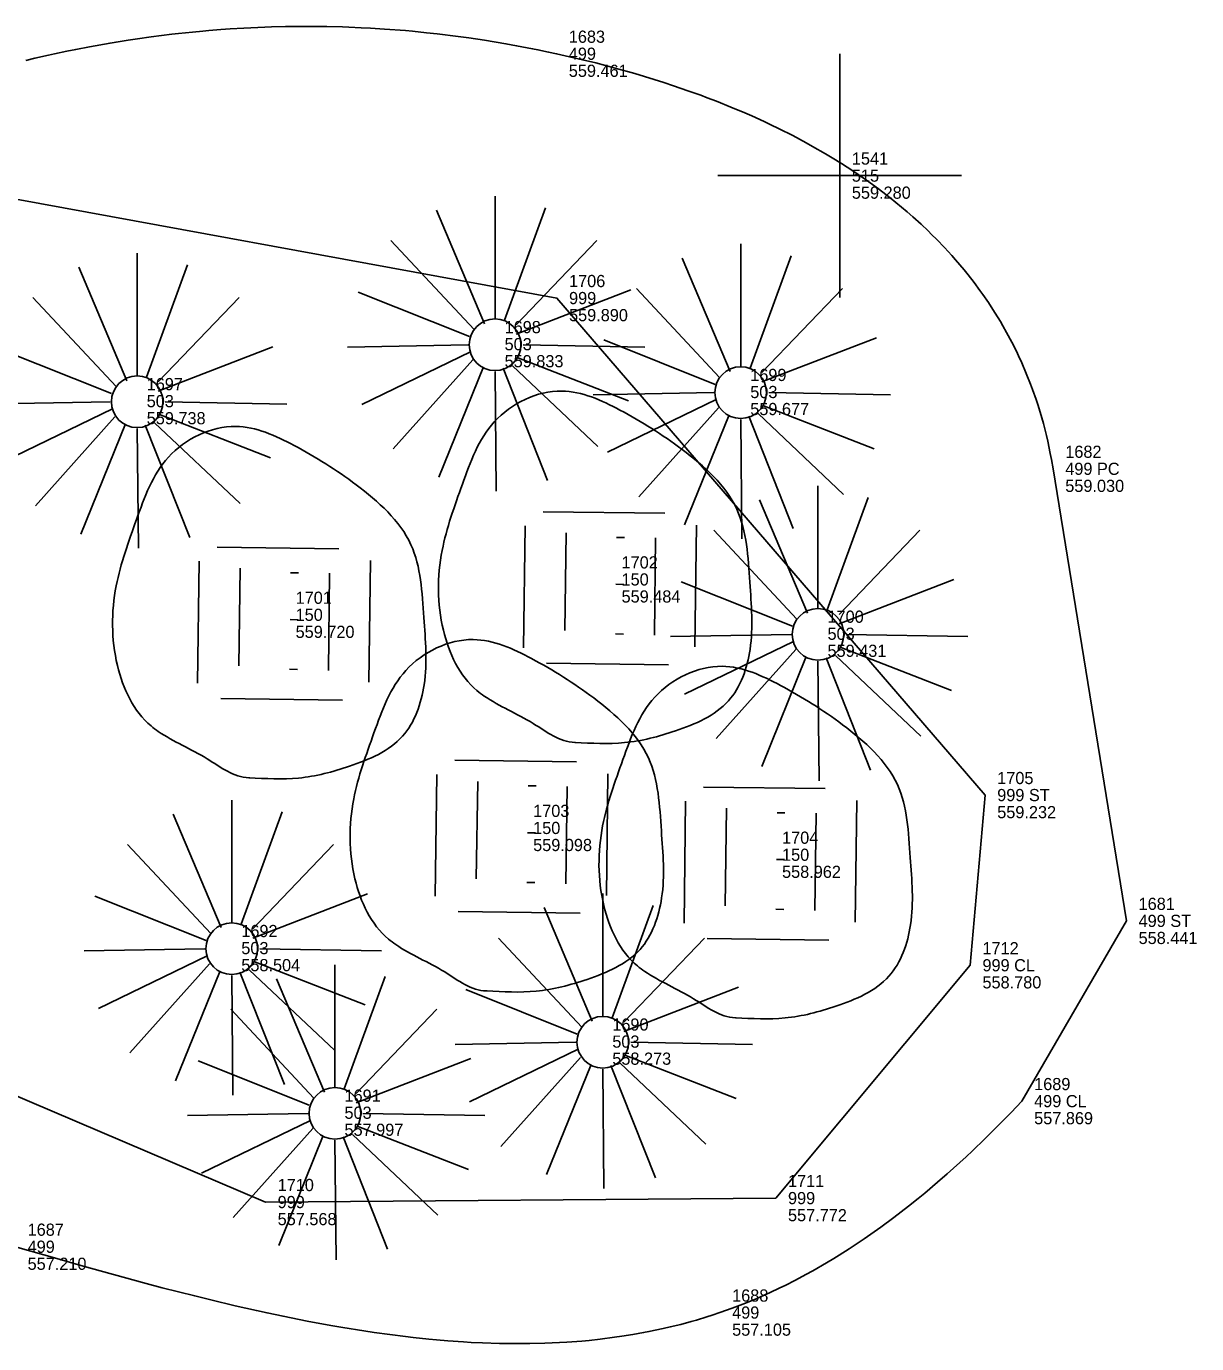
# Model space of a CAD drawing. Extents: x 5447 to 709667, y 4528 to 375505.
# Drawn here: x 707488.72 to 707512.75, y 374440.21 to 374467.25 of the extents above; entities that cross this region are included whole.
import ezdxf

# ---------------------------------------------------------------- set-up
doc = ezdxf.new("R2010")
doc.units = 0
for name, color, linetype in [('SV_BKLN_BKLN', 7, 'Continuous'), ('SV_NODES_ACTIVE_POINT', 7, 'Continuous'), ('SV_NODES_DESCRIPTION', 7, 'Continuous'), ('SV_NODES_ELEVATION', 7, 'Continuous'), ('SV_NODES_PT_NUMBER', 7, 'Continuous'), ('SV_ROCK_MISC_ROCK', 7, 'Continuous'), ('SV_SURF_SPOT', 7, 'Continuous'), ('SV_TREE_TREEVEG', 7, 'Continuous')]:
    doc.layers.add(name, color=color, linetype=linetype)

msp = doc.modelspace()

# ---------------------------------------------------------------- linework, layer by layer
at = {"layer": 'SV_BKLN_BKLN'}
msp.add_lwpolyline([(707508.404, 374451.469), (707499.614, 374461.672), (707487.053, 374463.971), (707478.999, 374458.382), (707479.555, 374449.113), (707493.632, 374443.114), (707504.109, 374443.195), (707508.101, 374447.975), (707508.404, 374451.469)], dxfattribs=at)
at = {"layer": 'SV_NODES_ACTIVE_POINT'}
for p, q in [((707499.609, 374466.688), (707499.609, 374466.688)), ((707499.614, 374461.672), (707499.614, 374461.672)), ((707509.801, 374458.167), (707509.801, 374458.167)), ((707508.404, 374451.469), (707508.404, 374451.469)), ((707511.306, 374448.886), (707511.306, 374448.886)), ((707508.101, 374447.975), (707508.101, 374447.975)), ((707509.162, 374445.186), (707509.162, 374445.186)), ((707504.109, 374443.195), (707504.109, 374443.195)), ((707493.632, 374443.114), (707493.632, 374443.114)), ((707502.962, 374440.845), (707502.962, 374440.845))]:
    msp.add_line(p, q, dxfattribs=at)
at = {"layer": 'SV_ROCK_MISC_ROCK'}
for p, q in [((707499.775, 374454.85), (707499.804, 374456.85)), ((707501.615, 374454.75), (707501.64, 374456.75)), ((707493.084, 374454.124), (707493.113, 374456.124)), ((707494.924, 374454.024), (707494.949, 374456.024)), ((707497.96, 374449.748), (707497.989, 374451.748)), ((707499.8, 374449.648), (707499.825, 374451.648)), ((707503.07, 374449.198), (707503.099, 374451.198)), ((707504.91, 374449.098), (707504.935, 374451.098))]:
    msp.add_line(p, q, dxfattribs=at)
for points in [[(707499.331, 374457.285), (707501.829, 374457.253)], [(707498.931, 374454.494), (707498.963, 374456.995)], [(707502.446, 374454.51), (707502.478, 374457.008)], [(707500.84, 374456.759), (707501.001, 374456.759)], [(707492.64, 374456.559), (707495.138, 374456.527)], [(707492.24, 374453.768), (707492.272, 374456.269)], [(707495.755, 374453.784), (707495.787, 374456.282)], [(707494.149, 374456.033), (707494.31, 374456.033)], [(707500.827, 374455.798), (707500.991, 374455.795)], [(707494.136, 374455.072), (707494.3, 374455.069)], [(707500.815, 374454.778), (707500.979, 374454.775)], [(707494.124, 374454.052), (707494.288, 374454.049)], [(707499.404, 374454.179), (707501.905, 374454.145)], [(707492.713, 374453.453), (707495.214, 374453.419)], [(707497.516, 374452.183), (707500.014, 374452.151)], [(707497.116, 374449.392), (707497.148, 374451.893)], [(707500.631, 374449.408), (707500.663, 374451.906)], [(707499.025, 374451.657), (707499.186, 374451.657)], [(707502.626, 374451.633), (707505.124, 374451.601)], [(707502.226, 374448.842), (707502.258, 374451.343)], [(707505.741, 374448.858), (707505.773, 374451.356)], [(707504.135, 374451.107), (707504.296, 374451.107)], [(707499.012, 374450.696), (707499.176, 374450.693)], [(707504.122, 374450.146), (707504.286, 374450.143)], [(707499, 374449.676), (707499.164, 374449.673)], [(707504.11, 374449.126), (707504.274, 374449.123)], [(707497.589, 374449.077), (707500.09, 374449.043)], [(707502.699, 374448.527), (707505.2, 374448.493)]]:
    msp.add_lwpolyline(points, dxfattribs=at)
for points in [[(707499.986, 374452.551), (707501.004, 374452.545), (707502.049, 374452.787), (707503.136, 374453.402), (707503.58, 374454.46), (707503.574, 374455.839), (707503.309, 374457.335), (707502.185, 374458.564), (707500.909, 374459.373), (707499.712, 374459.764), (707498.33, 374459.131), (707497.675, 374457.849), (707497.259, 374456.491), (707497.284, 374454.853), (707497.974, 374453.613), (707498.122, 374453.502), (707499.127, 374452.939), (707499.983, 374452.551), (707499.999, 374452.551)], [(707493.295, 374451.825), (707494.313, 374451.819), (707495.358, 374452.061), (707496.445, 374452.676), (707496.889, 374453.734), (707496.883, 374455.113), (707496.618, 374456.609), (707495.494, 374457.838), (707494.218, 374458.647), (707493.021, 374459.038), (707491.639, 374458.405), (707490.984, 374457.123), (707490.568, 374455.765), (707490.593, 374454.127), (707491.283, 374452.887), (707491.431, 374452.776), (707492.436, 374452.213), (707493.292, 374451.825), (707493.308, 374451.825)], [(707498.171, 374447.449), (707499.189, 374447.443), (707500.234, 374447.685), (707501.321, 374448.3), (707501.765, 374449.358), (707501.759, 374450.737), (707501.494, 374452.233), (707500.37, 374453.462), (707499.094, 374454.271), (707497.897, 374454.662), (707496.515, 374454.029), (707495.86, 374452.747), (707495.444, 374451.389), (707495.469, 374449.751), (707496.159, 374448.511), (707496.307, 374448.4), (707497.312, 374447.837), (707498.168, 374447.449), (707498.184, 374447.449)], [(707503.281, 374446.899), (707504.299, 374446.893), (707505.344, 374447.135), (707506.431, 374447.75), (707506.875, 374448.808), (707506.869, 374450.187), (707506.604, 374451.683), (707505.48, 374452.912), (707504.204, 374453.721), (707503.007, 374454.112), (707501.625, 374453.479), (707500.97, 374452.197), (707500.554, 374450.839), (707500.579, 374449.201), (707501.269, 374447.961), (707501.417, 374447.85), (707502.422, 374447.287), (707503.278, 374446.899), (707503.294, 374446.899)]]:
    msp.add_spline(points, degree=3, dxfattribs=at)
at = {"layer": 'SV_SURF_SPOT'}
for p, q in [((707505.42, 374461.685), (707505.42, 374466.687)), ((707502.919, 374464.186), (707507.921, 374464.186)), ((707505.42, 374464.186), (707505.42, 374464.186))]:
    msp.add_line(p, q, dxfattribs=at)
at = {"layer": 'SV_TREE_TREEVEG'}
for p, q in [((707498.345, 374461.243), (707498.345, 374463.765)), ((707497.145, 374463.476), (707498.13, 374461.145)), ((707499.378, 374463.523), (707498.537, 374461.217)), ((707496.206, 374462.852), (707497.913, 374461.025)), ((707498.779, 374461.123), (707500.436, 374462.852)), ((707503.388, 374460.261), (707503.388, 374462.783)), ((707490.998, 374460.073), (707490.998, 374462.595)), ((707502.188, 374462.494), (707503.173, 374460.163)), ((707504.421, 374462.541), (707503.58, 374460.235)), ((707489.798, 374462.306), (707490.783, 374459.975)), ((707492.031, 374462.353), (707491.19, 374460.047)), ((707498.779, 374460.931), (707501.132, 374461.841)), ((707501.249, 374461.87), (707502.956, 374460.043)), ((707503.822, 374460.141), (707505.479, 374461.87)), ((707488.859, 374461.682), (707490.566, 374459.855)), ((707491.432, 374459.953), (707493.089, 374461.682)), ((707497.819, 374460.88), (707495.535, 374461.794)), ((707502.862, 374459.898), (707500.578, 374460.812)), ((707503.822, 374459.949), (707506.175, 374460.859)), ((707490.472, 374459.71), (707488.188, 374460.624)), ((707491.432, 374459.761), (707493.785, 374460.671)), ((707497.793, 374460.713), (707495.318, 374460.666)), ((707497.841, 374460.569), (707495.608, 374459.488)), ((707498.921, 374460.713), (707501.419, 374460.666)), ((707497.888, 374460.402), (707496.256, 374458.575)), ((707498.105, 374460.257), (707497.192, 374457.998)), ((707498.511, 374460.232), (707499.425, 374457.926)), ((707498.704, 374460.282), (707500.458, 374458.622)), ((707498.801, 374460.449), (707501.085, 374459.561)), ((707498.345, 374460.162), (707498.37, 374457.709)), ((707502.836, 374459.731), (707500.361, 374459.684)), ((707503.964, 374459.731), (707506.462, 374459.684)), ((707490.446, 374459.543), (707487.971, 374459.496)), ((707491.574, 374459.543), (707494.072, 374459.496)), ((707502.884, 374459.587), (707500.651, 374458.506)), ((707502.931, 374459.42), (707501.299, 374457.593)), ((707503.844, 374459.467), (707506.128, 374458.579)), ((707490.494, 374459.399), (707488.261, 374458.318)), ((707490.541, 374459.232), (707488.909, 374457.405)), ((707491.454, 374459.279), (707493.738, 374458.391)), ((707503.148, 374459.275), (707502.235, 374457.016)), ((707503.388, 374459.18), (707503.413, 374456.727)), ((707503.554, 374459.25), (707504.468, 374456.944)), ((707503.747, 374459.3), (707505.501, 374457.64)), ((707490.758, 374459.087), (707489.845, 374456.828)), ((707490.998, 374458.992), (707491.023, 374456.539)), ((707491.164, 374459.062), (707492.078, 374456.756)), ((707491.357, 374459.112), (707493.111, 374457.452)), ((707504.974, 374455.298), (707504.974, 374457.82)), ((707503.774, 374457.531), (707504.759, 374455.2)), ((707506.007, 374457.578), (707505.166, 374455.272)), ((707502.835, 374456.907), (707504.542, 374455.08)), ((707505.408, 374455.178), (707507.065, 374456.907)), ((707505.408, 374454.986), (707507.761, 374455.896)), ((707504.448, 374454.935), (707502.164, 374455.849)), ((707504.422, 374454.768), (707501.947, 374454.721)), ((707504.47, 374454.624), (707502.237, 374453.543)), ((707505.55, 374454.768), (707508.048, 374454.721)), ((707504.517, 374454.457), (707502.885, 374452.63)), ((707504.734, 374454.312), (707503.821, 374452.053)), ((707505.14, 374454.287), (707506.054, 374451.981)), ((707505.333, 374454.337), (707507.087, 374452.677)), ((707505.43, 374454.504), (707507.714, 374453.616)), ((707504.974, 374454.217), (707504.999, 374451.764)), ((707492.94, 374448.845), (707492.94, 374451.367)), ((707491.74, 374451.078), (707492.725, 374448.747)), ((707493.973, 374451.125), (707493.132, 374448.819)), ((707490.801, 374450.454), (707492.508, 374448.627)), ((707493.374, 374448.725), (707495.031, 374450.454)), ((707492.414, 374448.482), (707490.13, 374449.396)), ((707493.374, 374448.533), (707495.727, 374449.443)), ((707500.556, 374446.925), (707500.556, 374449.447)), ((707499.356, 374449.158), (707500.341, 374446.827)), ((707501.589, 374449.205), (707500.748, 374446.899)), ((707492.388, 374448.315), (707489.913, 374448.268)), ((707493.516, 374448.315), (707496.014, 374448.268)), ((707498.417, 374448.534), (707500.124, 374446.707)), ((707500.99, 374446.805), (707502.647, 374448.534)), ((707492.436, 374448.171), (707490.203, 374447.09)), ((707493.396, 374448.051), (707495.68, 374447.163)), ((707492.483, 374448.004), (707490.851, 374446.177)), ((707492.7, 374447.859), (707491.787, 374445.6)), ((707493.106, 374447.834), (707494.02, 374445.528)), ((707493.299, 374447.884), (707495.053, 374446.224)), ((707495.058, 374445.465), (707495.058, 374447.987)), ((707492.94, 374447.764), (707492.965, 374445.311)), ((707493.858, 374447.698), (707494.843, 374445.367)), ((707496.091, 374447.745), (707495.25, 374445.439)), ((707500.99, 374446.613), (707503.343, 374447.523)), ((707500.03, 374446.562), (707497.746, 374447.476)), ((707492.919, 374447.074), (707494.626, 374445.247)), ((707495.492, 374445.345), (707497.149, 374447.074)), ((707500.004, 374446.395), (707497.529, 374446.348)), ((707500.052, 374446.251), (707497.819, 374445.17)), ((707501.132, 374446.395), (707503.63, 374446.348)), ((707494.532, 374445.102), (707492.248, 374446.016)), ((707495.492, 374445.153), (707497.845, 374446.063)), ((707500.099, 374446.084), (707498.467, 374444.257)), ((707500.316, 374445.939), (707499.403, 374443.68)), ((707500.722, 374445.914), (707501.636, 374443.608)), ((707500.915, 374445.964), (707502.669, 374444.304)), ((707501.012, 374446.131), (707503.296, 374445.243)), ((707500.556, 374445.844), (707500.581, 374443.391)), ((707494.506, 374444.935), (707492.031, 374444.888)), ((707495.634, 374444.935), (707498.132, 374444.888)), ((707494.554, 374444.791), (707492.321, 374443.71)), ((707494.601, 374444.624), (707492.969, 374442.797)), ((707495.514, 374444.671), (707497.798, 374443.783)), ((707494.818, 374444.479), (707493.905, 374442.22)), ((707495.058, 374444.384), (707495.083, 374441.931)), ((707495.224, 374444.454), (707496.138, 374442.148)), ((707495.417, 374444.504), (707497.171, 374442.844))]:
    msp.add_line(p, q, dxfattribs=at)
for points in [[(707511.306, 374448.886), (707509.801, 374458.167), (707509.768, 374458.358), (707509.744, 374458.483), (707509.691, 374458.731), (707509.663, 374458.854), (707509.601, 374459.095), (707509.533, 374459.331), (707509.485, 374459.487), (707509.451, 374459.589), (707509.38, 374459.792), (707509.338, 374459.904), (707509.25, 374460.125), (707509.157, 374460.342), (707509.092, 374460.485), (707509.047, 374460.579), (707508.954, 374460.764), (707508.845, 374460.968), (707508.769, 374461.102), (707508.718, 374461.191), (707508.611, 374461.365), (707508.529, 374461.494), (707508.473, 374461.578), (707508.359, 374461.745), (707508.3, 374461.828), (707508.18, 374461.99), (707508.056, 374462.149), (707507.972, 374462.254), (707507.799, 374462.459), (707507.724, 374462.544), (707507.571, 374462.711), (707507.414, 374462.874), (707507.308, 374462.98), (707507.236, 374463.051), (707507.09, 374463.189), (707506.922, 374463.341), (707506.808, 374463.44), (707506.575, 374463.634), (707506.457, 374463.729), (707506.215, 374463.914), (707505.969, 374464.093), (707505.801, 374464.208), (707505.688, 374464.284), (707505.46, 374464.432), (707505.264, 374464.553), (707505.132, 374464.632), (707504.865, 374464.786), (707504.729, 374464.861), (707504.456, 374465.006), (707504.179, 374465.146), (707503.993, 374465.237), (707503.867, 374465.295), (707503.615, 374465.41), (707503.472, 374465.473), (707503.184, 374465.594), (707502.894, 374465.711), (707502.699, 374465.786), (707502.569, 374465.835), (707502.306, 374465.929), (707502.01, 374466.032), (707501.812, 374466.097), (707501.413, 374466.222), (707501.213, 374466.281), (707500.813, 374466.394), (707500.411, 374466.499), (707500.143, 374466.565), (707499.609, 374466.688), (707499.444, 374466.723), (707499.224, 374466.769), (707499.114, 374466.791), (707498.786, 374466.853), (707498.567, 374466.892), (707498.131, 374466.964), (707497.805, 374467.013), (707497.587, 374467.043), (707497.154, 374467.096), (707496.938, 374467.12), (707496.65, 374467.149), (707496.506, 374467.162), (707496.075, 374467.195), (707495.788, 374467.213), (707495.598, 374467.223), (707495.343, 374467.234), (707495.216, 374467.238), (707494.895, 374467.246), (707494.682, 374467.249), (707494.397, 374467.25), (707494.255, 374467.249), (707494.042, 374467.246), (707493.758, 374467.24), (707493.616, 374467.235), (707493.191, 374467.216), (707492.908, 374467.198), (707492.719, 374467.185), (707492.468, 374467.165), (707492.343, 374467.154), (707492.131, 374467.134), (707491.849, 374467.104), (707491.708, 374467.088), (707491.285, 374467.035), (707491.004, 374466.995), (707490.816, 374466.967), (707490.566, 374466.927), (707490.441, 374466.906), (707490.02, 374466.831), (707489.739, 374466.777), (707489.552, 374466.739), (707489.303, 374466.686), (707489.178, 374466.659), (707488.897, 374466.595), (707488.711, 374466.551)], [(707488.499, 374442.197), (707489.395, 374441.939), (707489.843, 374441.812), (707490.513, 374441.625), (707491.181, 374441.444), (707491.514, 374441.356), (707492.179, 374441.186), (707492.511, 374441.104), (707493.007, 374440.986), (707493.447, 374440.887), (707493.666, 374440.839), (707493.994, 374440.769), (707494.485, 374440.671), (707494.974, 374440.581), (707495.217, 374440.539), (707495.649, 374440.469), (707495.863, 374440.437), (707496.185, 374440.393), (707496.505, 374440.353), (707496.665, 374440.334), (707496.983, 374440.301), (707497.142, 374440.286), (707497.379, 374440.266), (707497.695, 374440.243), (707497.852, 374440.234), (707498.087, 374440.223), (707498.438, 374440.211), (707498.714, 374440.207), (707498.851, 374440.207), (707499.057, 374440.209), (707499.364, 374440.216), (707499.67, 374440.229), (707499.822, 374440.238), (707500.125, 374440.261), (707500.276, 374440.275), (707500.501, 374440.299), (707500.8, 374440.337), (707500.949, 374440.358), (707501.172, 374440.394), (707501.393, 374440.433), (707501.503, 374440.454), (707501.795, 374440.516), (707501.941, 374440.549), (707502.158, 374440.603), (707502.374, 374440.662), (707502.482, 374440.692), (707502.696, 374440.757), (707502.803, 374440.791), (707502.962, 374440.845), (707503.212, 374440.933), (707503.377, 374440.996), (707503.486, 374441.04), (707503.705, 374441.13), (707503.868, 374441.201), (707503.976, 374441.25), (707504.192, 374441.351), (707504.299, 374441.403), (707504.512, 374441.511), (707504.725, 374441.624), (707504.866, 374441.702), (707505.146, 374441.863), (707505.302, 374441.957), (707505.406, 374442.021), (707505.614, 374442.153), (707505.717, 374442.22), (707505.922, 374442.358), (707506.127, 374442.5), (707506.262, 374442.597), (707506.532, 374442.796), (707506.833, 374443.029), (707507.033, 374443.189), (707507.165, 374443.297), (707507.429, 374443.52), (707507.625, 374443.691), (707507.756, 374443.807), (707508.015, 374444.044), (707508.144, 374444.165), (707508.401, 374444.412), (707508.656, 374444.664), (707508.826, 374444.836), (707508.938, 374444.951), (707509.162, 374445.186), (707511.306, 374448.886)]]:
    msp.add_lwpolyline(points, dxfattribs=at)
for centre in [(707498.345, 374460.713), (707503.388, 374459.731), (707490.998, 374459.543), (707504.974, 374454.768), (707492.94, 374448.315), (707500.556, 374446.395), (707495.058, 374444.935)]:
    msp.add_circle(centre, 0.53, dxfattribs=at)

# ---------------------------------------------------------------- texts
at = {"layer": 'SV_NODES_DESCRIPTION'}
for s, p in [('499', (707499.859, 374466.563)), ('515', (707505.67, 374464.061)), ('999', (707499.864, 374461.547)), ('503', (707498.541, 374460.601)), ('503', (707491.194, 374459.431)), ('503', (707503.584, 374459.619)), ('499 PC', (707510.051, 374458.042)), ('150', (707500.942, 374455.771)), ('150', (707494.251, 374455.045)), ('503', (707505.17, 374454.656)), ('999 ST', (707508.654, 374451.344)), ('150', (707499.127, 374450.669)), ('150', (707504.237, 374450.119)), ('499 ST', (707511.556, 374448.761)), ('503', (707493.136, 374448.203)), ('999 CL', (707508.351, 374447.85)), ('503', (707500.752, 374446.283)), ('503', (707495.254, 374444.823)), ('499 CL', (707509.412, 374445.061)), ('999', (707493.882, 374442.989)), ('999', (707504.359, 374443.07)), ('499', (707488.749, 374442.072)), ('499', (707503.212, 374440.72))]:
    msp.add_text(s, height=0.25, dxfattribs=at).set_placement(p)
at = {"layer": 'SV_NODES_ELEVATION'}
for s, p in [('559.461', (707499.859, 374466.213)), ('559.280', (707505.67, 374463.711)), ('559.890', (707499.864, 374461.197)), ('559.833', (707498.541, 374460.251)), ('559.677', (707503.584, 374459.269)), ('559.738', (707491.194, 374459.081)), ('559.030', (707510.051, 374457.692)), ('559.484', (707500.942, 374455.421)), ('559.720', (707494.251, 374454.695)), ('559.431', (707505.17, 374454.306)), ('559.232', (707508.654, 374450.994)), ('559.098', (707499.127, 374450.319)), ('558.962', (707504.237, 374449.769)), ('558.441', (707511.556, 374448.411)), ('558.504', (707493.136, 374447.853)), ('558.780', (707508.351, 374447.5)), ('558.273', (707500.752, 374445.933)), ('557.869', (707509.412, 374444.711)), ('557.997', (707495.254, 374444.473)), ('557.772', (707504.359, 374442.72)), ('557.568', (707493.882, 374442.639)), ('557.210', (707488.749, 374441.722)), ('557.105', (707503.212, 374440.37))]:
    msp.add_text(s, height=0.25, dxfattribs=at).set_placement(p)
at = {"layer": 'SV_NODES_PT_NUMBER'}
for s, p in [('1683', (707499.859, 374466.913)), ('1541', (707505.67, 374464.411)), ('1706', (707499.864, 374461.897)), ('1698', (707498.541, 374460.951)), ('1699', (707503.584, 374459.969)), ('1697', (707491.194, 374459.781)), ('1682', (707510.051, 374458.392)), ('1702', (707500.942, 374456.121)), ('1701', (707494.251, 374455.395)), ('1700', (707505.17, 374455.006)), ('1705', (707508.654, 374451.694)), ('1703', (707499.127, 374451.019)), ('1704', (707504.237, 374450.469)), ('1681', (707511.556, 374449.111)), ('1692', (707493.136, 374448.553)), ('1712', (707508.351, 374448.2)), ('1690', (707500.752, 374446.633)), ('1689', (707509.412, 374445.411)), ('1691', (707495.254, 374445.173)), ('1710', (707493.882, 374443.339)), ('1711', (707504.359, 374443.42)), ('1687', (707488.749, 374442.422)), ('1688', (707503.212, 374441.07))]:
    msp.add_text(s, height=0.25, dxfattribs=at).set_placement(p)

doc.saveas('drawing.dxf')
